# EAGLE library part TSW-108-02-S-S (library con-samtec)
THROUGH-HOLE .025" SQ POST HEADER Source: Samtec TSW.pdf
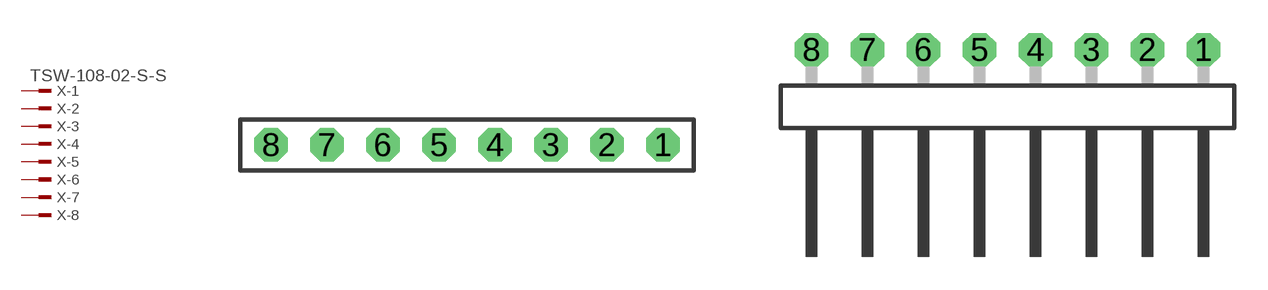
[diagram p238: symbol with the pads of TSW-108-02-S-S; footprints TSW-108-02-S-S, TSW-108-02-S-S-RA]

Designator prefix X; gates -1=MPINV -2=MPIN -3=MPIN -4=MPIN -5=MPIN -6=MPIN -7=MPIN -8=MPIN

## TSW-108-02-S-S (OC_FARNELL: unknown; OC_NEWARK: unknown)  [TSW-108-02-S-S]
1  -1:1  pas
2  -2:1  pas
3  -3:1  pas
4  -4:1  pas
5  -5:1  pas
6  -6:1  pas
7  -7:1  pas
8  -8:1  pas

## TSW-108-02-S-S-RA (OC_FARNELL: unknown; OC_NEWARK: unknown)  [TSW-108-02-S-S-RA]
Pads as for TSW-108-02-S-S

## Footprint TSW-108-02-S-S (pad centres in mm)
THROUGH-HOLE .025" SQ POST HEADER Source: Samtec TSW.pdf
drill 1 pad 1.5 octagon: 1 8.89,0; 2 6.35,0; 3 3.81,0; 4 1.27,0; 5 -1.27,0; 6 -3.81,0; 7 -6.35,0; 8 -8.89,0

## Footprint TSW-108-02-S-S-RA (pad centres in mm)
THROUGH-HOLE .025" SQ POST HEADER Source: Samtec TSW.pdf
drill 1 pad 1.5 octagon: 1 8.89,1.524; 2 6.35,1.524; 3 3.81,1.524; 4 1.27,1.524; 5 -1.27,1.524; 6 -3.81,1.524; 7 -6.35,1.524; 8 -8.89,1.524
